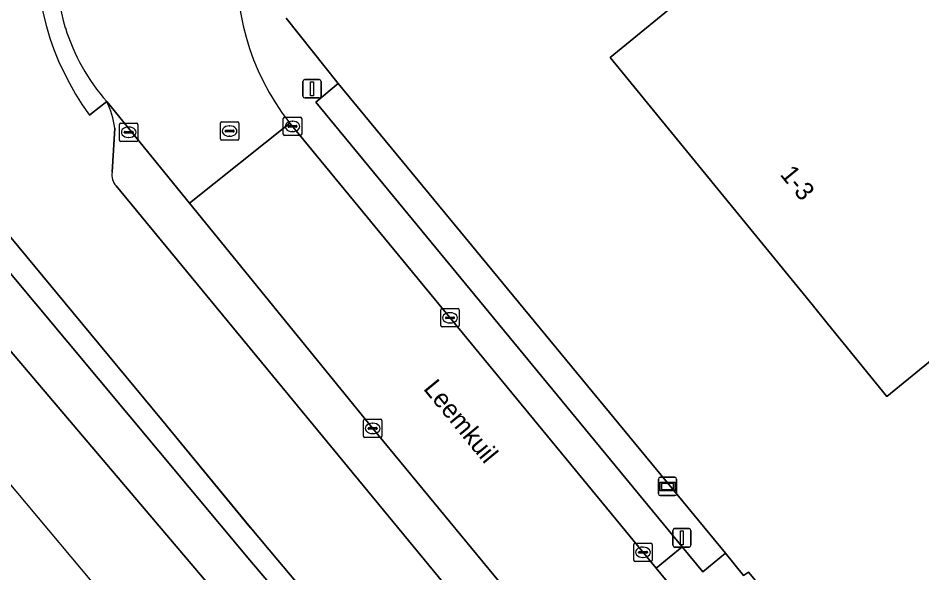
# Model space of a CAD drawing. Extents: x 156702 to 158052, y 387630 to 388992.
# Drawn here: x 156930.1 to 156979.28, y 388126.02 to 388156.23 of the extents above; entities that cross this region are included whole.
import ezdxf

# ---------------------------------------------------------------- set-up
doc = ezdxf.new("R2010")
doc.units = 0
for name, color, linetype in [('IMGEO_Berm_groen', 7, 'Continuous'), ('IMGEO_Erf', 7, 'Continuous'), ('IMGEO_Grasland_overig', 7, 'Continuous'), ('IMGEO_Groenvoorziening', 7, 'Continuous'), ('IMGEO_Hek', 7, 'Continuous'), ('IMGEO_Kolk', 7, 'Continuous'), ('IMGEO_Lichtmast', 7, 'Continuous'), ('IMGEO_Muur', 7, 'Continuous'), ('IMGEO_Openbare_ruimte_label', 7, 'Continuous'), ('IMGEO_Pand', 7, 'Continuous'), ('IMGEO_Pand_nummerreeks', 7, 'Continuous'), ('IMGEO_Parkeervlak_open', 7, 'Continuous'), ('IMGEO_Rijbaan_lokaal_gesloten', 7, 'Continuous'), ('IMGEO_Rioolput', 7, 'Continuous'), ('IMGEO_Spoor', 7, 'Continuous'), ('IMGEO_Spoorbaan_halfverhard', 7, 'Continuous'), ('IMGEO_Verkeerseiland_open', 7, 'Continuous'), ('IMGEO_Verklikker', 7, 'Continuous'), ('IMGEO_Voetpad_open', 7, 'Continuous')]:
    doc.layers.add(name, color=color, linetype=linetype)

msp = doc.modelspace()

# ---------------------------------------------------------------- linework, layer by layer
at = {"layer": 'IMGEO_Berm_groen'}
for points in [[(156896.099, 388207.526), (156898, 388209.126), (156929.184, 388170.168), (156924.251, 388165.972), (156893.783, 388204.247), (156893.53, 388204.428), (156892.646, 388205.059), (156888.807, 388202.728), (156887.763, 388201.954), (156884.553, 388200.49), (156886.404, 388196.476), (156888.178, 388194.608), (156891.399, 388190.784), (156894.533, 388186.892), (156900.926, 388179.065), (156905.729, 388173.299), (156910.538, 388167.48), (156920.203, 388155.732), (156923.432, 388151.842), (156933.092, 388140.181), (156937.906, 388134.372), (156942.722, 388128.504), (156944.225, 388126.72), (156950.711, 388119.018)], [(156934.916, 388151.692), (156934.087, 388151.032), (156933.977, 388150.944)], [(156935.21, 388147.831), (156935.356, 388150.243)], [(157082.395, 387968.454), (157010.543, 388055.913), (156935.425, 388147.089)]]:
    msp.add_lwpolyline(points, dxfattribs=at)
for centre, radius, start, end in [((156946.293, 388159.895), 15.225, 136.0002, 216.0083), ((156931.068, 388149.732), 4.318, 6.792, 26.9906), ((156936.179, 388147.71), 0.977, 172.8704, 219.4483)]:
    msp.add_arc(centre, radius, start, end, dxfattribs=at)
at = {"layer": 'IMGEO_Erf'}
for points in [[(156982.599, 388139.887), (156977.372, 388135.617), (156974.12, 388139.625), (156973.299, 388140.637), (156962.306, 388154.079), (156967.472, 388158.304), (156963.056, 388163.663), (156979.678, 388177.353)], [(156944.674, 388156.23), (156947.515, 388152.662), (156968.59, 388127.099), (156969.571, 388125.885), (156969.838, 388126.064), (156973.576, 388121.584)]]:
    msp.add_lwpolyline(points, dxfattribs=at)
at = {"layer": 'IMGEO_Grasland_overig'}
for points in [[(156950.711, 388119.018), (156944.225, 388126.72), (156942.722, 388128.504), (156937.906, 388134.372), (156933.092, 388140.181), (156923.432, 388151.842), (156920.203, 388155.732), (156910.538, 388167.48), (156905.729, 388173.299), (156900.926, 388179.065), (156894.533, 388186.892), (156891.399, 388190.784), (156888.178, 388194.608), (156886.404, 388196.476), (156884.553, 388200.49), (156883.204, 388198.755), (156897.934, 388180.367), (156942.697, 388126.718), (156967.711, 388097.26)], [(156967.711, 388097.26), (156942.697, 388126.718), (156897.934, 388180.367), (156883.204, 388198.755), (156881.34, 388197.231), (156885.921, 388191.403), (156911.81, 388159.683), (156929.103, 388138.77), (156962.414, 388099.504)]]:
    msp.add_lwpolyline(points, dxfattribs=at)
at = {"layer": 'IMGEO_Groenvoorziening'}
msp.add_lwpolyline([(156968.59, 388127.099), (156947.515, 388152.662), (156946.293, 388151.648), (156966.232, 388127.436), (156967.347, 388126.077)], close=True, dxfattribs=at)
at = {"layer": 'IMGEO_Hek'}
msp.add_lwpolyline([(156881.352, 388206.869), (156882.652, 388204.634), (156884.272, 388200.902), (156886.31, 388196.524), (156888.129, 388194.659), (156896.125, 388184.896), (156905.748, 388173.218), (156912.203, 388165.408), (156918.6, 388157.648), (156928.233, 388146.023), (156937.874, 388134.379), (156942.73, 388128.478)], dxfattribs=at)
at = {"layer": 'IMGEO_Kolk'}
for p, q in [((156944.601, 388150.832), (156945.453, 388150.832)), ((156935.614, 388149.587), (156935.614, 388150.439)), ((156935.689, 388150.513), (156936.541, 388150.513)), ((156936.615, 388150.439), (156936.615, 388149.587)), ((156944.526, 388149.906), (156944.526, 388150.758)), ((156944.785, 388150.326), (156944.785, 388150.338)), ((156944.828, 388150.375), (156945.226, 388150.375)), ((156945.014, 388150.612), (156945.039, 388150.612)), ((156945.269, 388150.338), (156945.269, 388150.326)), ((156945.527, 388150.758), (156945.527, 388149.906)), ((156935.873, 388150.007), (156935.873, 388150.019)), ((156936.311, 388149.97), (156935.913, 388149.97)), ((156935.916, 388150.056), (156936.314, 388150.056)), ((156936.102, 388150.293), (156936.127, 388150.293)), ((156936.357, 388150.019), (156936.357, 388150.007)), ((156945.453, 388149.832), (156944.601, 388149.832)), ((156945.223, 388150.289), (156944.825, 388150.289)), ((156945.037, 388150.052), (156945.012, 388150.052)), ((156936.541, 388149.513), (156935.689, 388149.513)), ((156936.125, 388149.733), (156936.1, 388149.733)), ((156953.096, 388139.484), (156953.096, 388140.336)), ((156953.171, 388140.41), (156954.023, 388140.41)), ((156953.584, 388140.19), (156953.609, 388140.19)), ((156954.097, 388140.336), (156954.097, 388139.484)), ((156953.355, 388139.904), (156953.355, 388139.916)), ((156953.793, 388139.867), (156953.395, 388139.867)), ((156953.398, 388139.953), (156953.796, 388139.953)), ((156953.607, 388139.63), (156953.582, 388139.63)), ((156953.839, 388139.916), (156953.839, 388139.904)), ((156954.023, 388139.41), (156953.171, 388139.41)), ((156948.889, 388133.462), (156948.889, 388134.314)), ((156948.964, 388134.388), (156949.816, 388134.388)), ((156949.377, 388134.168), (156949.402, 388134.168)), ((156949.89, 388134.314), (156949.89, 388133.462)), ((156949.148, 388133.882), (156949.148, 388133.894)), ((156949.586, 388133.845), (156949.188, 388133.845)), ((156949.191, 388133.931), (156949.589, 388133.931)), ((156949.4, 388133.608), (156949.375, 388133.608)), ((156949.632, 388133.894), (156949.632, 388133.882)), ((156949.816, 388133.388), (156948.964, 388133.388)), ((156963.599, 388126.717), (156963.599, 388127.569)), ((156963.674, 388127.643), (156964.526, 388127.643)), ((156963.901, 388127.186), (156964.299, 388127.186)), ((156964.087, 388127.423), (156964.112, 388127.423)), ((156964.6, 388127.569), (156964.6, 388126.717)), ((156963.858, 388127.137), (156963.858, 388127.149)), ((156964.296, 388127.1), (156963.898, 388127.1)), ((156964.11, 388126.863), (156964.085, 388126.863)), ((156964.342, 388127.149), (156964.342, 388127.137)), ((156964.526, 388126.643), (156963.674, 388126.643))]:
    msp.add_line(p, q, dxfattribs=at)
for points in [[(156944.601, 388150.832), (156945.453, 388150.832)], [(156935.614, 388149.587), (156935.614, 388150.439)], [(156935.689, 388150.513), (156936.541, 388150.513)], [(156936.615, 388150.439), (156936.615, 388149.587)], [(156944.526, 388149.906), (156944.526, 388150.758)], [(156945.527, 388150.758), (156945.527, 388149.906)], [(156945.453, 388149.832), (156944.601, 388149.832)], [(156936.541, 388149.513), (156935.689, 388149.513)], [(156953.096, 388139.484), (156953.096, 388140.336)], [(156953.171, 388140.41), (156954.023, 388140.41)], [(156954.097, 388140.336), (156954.097, 388139.484)], [(156954.023, 388139.41), (156953.171, 388139.41)], [(156948.889, 388133.462), (156948.889, 388134.314)], [(156948.964, 388134.388), (156949.816, 388134.388)], [(156949.89, 388134.314), (156949.89, 388133.462)], [(156949.816, 388133.388), (156948.964, 388133.388)], [(156963.599, 388126.717), (156963.599, 388127.569)], [(156963.674, 388127.643), (156964.526, 388127.643)], [(156964.6, 388127.569), (156964.6, 388126.717)], [(156964.526, 388126.643), (156963.674, 388126.643)]]:
    msp.add_lwpolyline(points, dxfattribs=at)
for centre, radius, start, end in [((156944.603, 388150.756), 0.0765, 91.552, 178.448), ((156944.603, 388150.756), 0.0765, 91.552, 178.448), ((156945.451, 388150.756), 0.0765, 1.552, 88.448), ((156945.451, 388150.756), 0.0765, 1.552, 88.448), ((156935.691, 388150.437), 0.0765, 91.552, 178.448), ((156935.691, 388150.437), 0.0765, 91.552, 178.448), ((156936.539, 388150.437), 0.0765, 1.552, 88.448), ((156936.539, 388150.437), 0.0765, 1.552, 88.448), ((156944.825, 388150.335), 0.0403, 85.8775, 175.7526), ((156944.822, 388150.325), 0.0366, 178.938, 274.7102), ((156945.226, 388150.332), 0.043, 264.8664, 352.4533), ((156945.23, 388150.337), 0.0386, 1.7309, 96.639), ((156935.913, 388150.016), 0.0403, 85.8775, 175.7526), ((156935.91, 388150.006), 0.0366, 178.938, 274.7102), ((156936.314, 388150.013), 0.043, 264.8664, 352.4533), ((156936.318, 388150.018), 0.0386, 1.7309, 96.639), ((156944.603, 388149.908), 0.0765, 181.552, 268.448), ((156944.603, 388149.908), 0.0765, 181.552, 268.448), ((156945.451, 388149.908), 0.0765, 271.552, 358.448), ((156945.451, 388149.908), 0.0765, 271.552, 358.448), ((156935.691, 388149.589), 0.0765, 181.552, 268.448), ((156935.691, 388149.589), 0.0765, 181.552, 268.448), ((156936.539, 388149.589), 0.0765, 271.552, 358.448), ((156936.539, 388149.589), 0.0765, 271.552, 358.448), ((156953.173, 388140.334), 0.0765, 91.552, 178.448), ((156953.173, 388140.334), 0.0765, 91.552, 178.448), ((156954.021, 388140.334), 0.0765, 1.552, 88.448), ((156954.021, 388140.334), 0.0765, 1.552, 88.448), ((156953.173, 388139.486), 0.0765, 181.552, 268.448), ((156953.173, 388139.486), 0.0765, 181.552, 268.448), ((156953.395, 388139.913), 0.0403, 85.8775, 175.7526), ((156953.392, 388139.903), 0.0366, 178.938, 274.7102), ((156953.796, 388139.91), 0.043, 264.8664, 352.4533), ((156953.8, 388139.915), 0.0386, 1.7309, 96.639), ((156954.021, 388139.486), 0.0765, 271.552, 358.448), ((156954.021, 388139.486), 0.0765, 271.552, 358.448), ((156948.966, 388134.312), 0.0765, 91.552, 178.448), ((156948.966, 388134.312), 0.0765, 91.552, 178.448), ((156949.814, 388134.312), 0.0765, 1.552, 88.448), ((156949.814, 388134.312), 0.0765, 1.552, 88.448), ((156949.188, 388133.891), 0.0403, 85.8775, 175.7526), ((156949.185, 388133.881), 0.0366, 178.938, 274.7102), ((156949.589, 388133.888), 0.043, 264.8664, 352.4533), ((156949.593, 388133.893), 0.0386, 1.7309, 96.639), ((156948.966, 388133.464), 0.0765, 181.552, 268.448), ((156948.966, 388133.464), 0.0765, 181.552, 268.448), ((156949.814, 388133.464), 0.0765, 271.552, 358.448), ((156949.814, 388133.464), 0.0765, 271.552, 358.448), ((156963.676, 388127.567), 0.0765, 91.552, 178.448), ((156963.676, 388127.567), 0.0765, 91.552, 178.448), ((156963.898, 388127.146), 0.0403, 85.8775, 175.7526), ((156964.303, 388127.148), 0.0386, 1.7309, 96.639), ((156964.524, 388127.567), 0.0765, 1.552, 88.448), ((156964.524, 388127.567), 0.0765, 1.552, 88.448), ((156963.676, 388126.719), 0.0765, 181.552, 268.448), ((156963.676, 388126.719), 0.0765, 181.552, 268.448), ((156963.895, 388127.136), 0.0366, 178.938, 274.7102), ((156964.299, 388127.143), 0.043, 264.8664, 352.4533), ((156964.524, 388126.719), 0.0765, 271.552, 358.448), ((156964.524, 388126.719), 0.0765, 271.552, 358.448)]:
    msp.add_arc(centre, radius, start, end, dxfattribs=at)
for centre, major_axis, ratio, start_param, end_param in [((156936.101, 388150.013), (-0.387, 0.002), 0.722429, 4.712389, 7.853982), ((156945.013, 388150.332), (-0.387, 0.002), 0.722429, 4.712389, 7.853982), ((156945.038, 388150.332), (-0.39, 0.002), 0.717154, 1.570796, 4.712389), ((156936.126, 388150.013), (-0.39, 0.002), 0.717154, 1.570796, 4.712389), ((156953.583, 388139.91), (-0.387, 0.002), 0.722429, 4.712389, 7.853982), ((156953.608, 388139.91), (-0.39, 0.002), 0.717154, 1.570796, 4.712389), ((156949.376, 388133.888), (-0.387, 0.002), 0.722429, 4.712389, 7.853982), ((156949.401, 388133.888), (-0.39, 0.002), 0.717154, 1.570796, 4.712389), ((156964.086, 388127.143), (-0.387, 0.002), 0.722429, 4.712389, 7.853982), ((156964.111, 388127.143), (-0.39, 0.002), 0.717154, 1.570796, 4.712389)]:
    msp.add_ellipse(centre, major_axis=major_axis, ratio=ratio, start_param=start_param, end_param=end_param, dxfattribs=at)
at = {"layer": 'IMGEO_Lichtmast'}
for p, q in [((156945.594, 388151.978), (156945.594, 388152.778)), ((156945.594, 388152.778), (156945.594, 388151.978)), ((156945.694, 388152.878), (156946.484, 388152.878)), ((156946.484, 388152.878), (156945.694, 388152.878)), ((156946.584, 388152.778), (156946.584, 388151.978)), ((156946.584, 388151.978), (156946.584, 388152.778)), ((156946.484, 388151.878), (156945.694, 388151.878)), ((156945.694, 388151.878), (156946.484, 388151.878)), ((156965.721, 388127.53), (156965.721, 388128.33)), ((156965.721, 388128.33), (156965.721, 388127.53)), ((156965.821, 388128.43), (156966.611, 388128.43)), ((156966.611, 388128.43), (156965.821, 388128.43)), ((156966.711, 388128.33), (156966.711, 388127.53)), ((156966.711, 388127.53), (156966.711, 388128.33)), ((156966.611, 388127.43), (156965.821, 388127.43)), ((156965.821, 388127.43), (156966.611, 388127.43))]:
    msp.add_line(p, q, dxfattribs=at)
for points in [[(156946.014, 388152.753), (156946.164, 388152.753), (156946.164, 388152.003), (156946.014, 388152.003), (156946.014, 388152.753)], [(156966.141, 388128.305), (156966.291, 388128.305), (156966.291, 388127.555), (156966.141, 388127.555), (156966.141, 388128.305)]]:
    msp.add_lwpolyline(points, dxfattribs=at)
for centre, start, end in [((156945.694, 388152.778), 90, 180), ((156945.694, 388152.778), 90, 180), ((156946.484, 388152.778), 0, 90), ((156946.484, 388152.778), 360, 90), ((156945.694, 388151.978), 180, 270), ((156945.694, 388151.978), 180, 270), ((156946.484, 388151.978), 270, 0), ((156946.484, 388151.978), 270, 0), ((156965.821, 388128.33), 90, 180), ((156965.821, 388128.33), 90, 180), ((156966.611, 388128.33), 0, 90), ((156966.611, 388128.33), 360, 90), ((156965.821, 388127.53), 180, 270), ((156965.821, 388127.53), 180, 270), ((156966.611, 388127.53), 270, 0), ((156966.611, 388127.53), 270, 0)]:
    msp.add_arc(centre, 0.1, start, end, dxfattribs=at)
at = {"layer": 'IMGEO_Muur'}
msp.add_lwpolyline([(156884.553, 388200.49), (156886.404, 388196.476), (156888.178, 388194.608), (156891.399, 388190.784), (156894.533, 388186.892), (156900.926, 388179.065), (156905.729, 388173.299), (156910.538, 388167.48), (156920.203, 388155.732), (156923.432, 388151.842), (156933.092, 388140.181), (156937.906, 388134.372), (156942.722, 388128.504), (156944.225, 388126.72), (156950.711, 388119.018)], dxfattribs=at)
at = {"layer": 'IMGEO_Pand'}
msp.add_lwpolyline([(156979.678, 388177.353), (156963.056, 388163.663), (156967.472, 388158.304), (156962.306, 388154.079), (156973.299, 388140.637), (156974.12, 388139.625), (156977.372, 388135.617), (156982.599, 388139.887), (156986.971, 388134.536), (157000, 388145.263), (157003.589, 388148.218), (157000, 388152.592)], close=True, dxfattribs=at)
at = {"layer": 'IMGEO_Parkeervlak_open'}
for points in [[(156975.736, 388101.937), (156949.39, 388133.888), (156939.424, 388146.146), (156934.916, 388151.692)], [(156935.356, 388150.243), (156935.21, 388147.831)], [(156935.425, 388147.089), (157010.543, 388055.913), (157082.395, 387968.454)]]:
    msp.add_lwpolyline(points, dxfattribs=at)
for centre, radius, start, end in [((156931.068, 388149.732), 4.318, 6.792, 26.9906), ((156936.179, 388147.71), 0.977, 172.8704, 219.4483)]:
    msp.add_arc(centre, radius, start, end, dxfattribs=at)
at = {"layer": 'IMGEO_Rijbaan_lokaal_gesloten'}
for points in [[(156934.916, 388151.692), (156939.424, 388146.146), (156944.879, 388150.503)], [(156973.268, 388116.017), (156964.812, 388126.277), (156944.879, 388150.503), (156939.424, 388146.146), (156949.39, 388133.888), (156975.736, 388101.937)]]:
    msp.add_lwpolyline(points, dxfattribs=at)
for centre, radius, start, end in [((156955.642, 388158.903), 13.653, 130.6832, 217.97), ((156944.671, 388159.255), 12.52, 166.7289, 196.4964), ((156943.228, 388158.991), 11.062, 197.3081, 221.2879)]:
    msp.add_arc(centre, radius, start, end, dxfattribs=at)
at = {"layer": 'IMGEO_Rioolput'}
for p, q in [((156941.102, 388149.651), (156941.102, 388150.503)), ((156941.177, 388150.577), (156942.029, 388150.577)), ((156941.59, 388150.357), (156941.615, 388150.357)), ((156942.103, 388150.503), (156942.103, 388149.651)), ((156941.361, 388150.071), (156941.361, 388150.083)), ((156941.799, 388150.034), (156941.401, 388150.034)), ((156941.404, 388150.12), (156941.802, 388150.12)), ((156941.845, 388150.083), (156941.845, 388150.071)), ((156942.029, 388149.577), (156941.177, 388149.577)), ((156941.613, 388149.797), (156941.588, 388149.797))]:
    msp.add_line(p, q, dxfattribs=at)
for points in [[(156941.102, 388149.651), (156941.102, 388150.503)], [(156941.177, 388150.577), (156942.029, 388150.577)], [(156942.103, 388150.503), (156942.103, 388149.651)], [(156942.029, 388149.577), (156941.177, 388149.577)]]:
    msp.add_lwpolyline(points, dxfattribs=at)
for centre, radius, start, end in [((156941.179, 388150.501), 0.0765, 91.552, 178.448), ((156941.179, 388150.501), 0.0765, 91.552, 178.448), ((156942.027, 388150.501), 0.0765, 1.552, 88.448), ((156942.027, 388150.501), 0.0765, 1.552, 88.448), ((156941.401, 388150.08), 0.0403, 85.8775, 175.7526), ((156941.398, 388150.07), 0.0366, 178.938, 274.7102), ((156941.802, 388150.077), 0.043, 264.8664, 352.4533), ((156941.806, 388150.082), 0.0386, 1.7309, 96.639), ((156941.179, 388149.653), 0.0765, 181.552, 268.448), ((156941.179, 388149.653), 0.0765, 181.552, 268.448), ((156942.027, 388149.653), 0.0765, 271.552, 358.448), ((156942.027, 388149.653), 0.0765, 271.552, 358.448)]:
    msp.add_arc(centre, radius, start, end, dxfattribs=at)
for centre, major_axis, ratio, start_param, end_param in [((156941.589, 388150.077), (-0.387, 0.002), 0.722429, 4.712389, 7.853982), ((156941.614, 388150.077), (-0.39, 0.002), 0.717154, 1.570796, 4.712389)]:
    msp.add_ellipse(centre, major_axis=major_axis, ratio=ratio, start_param=start_param, end_param=end_param, dxfattribs=at)
at = {"layer": 'IMGEO_Spoor'}
msp.add_lwpolyline([(156872.422, 388201.343), (156882.919, 388187.987), (156900.381, 388166.18), (156921.457, 388140.635), (156943.252, 388114.607), (156960.211, 388094.663), (156986.26, 388064.316), (157082.584, 387953.12), (157127.585, 387900.649), (157147.691, 387876.906), (157152.061, 387871.615)], dxfattribs=at)
at = {"layer": 'IMGEO_Spoorbaan_halfverhard'}
msp.add_lwpolyline([(156962.414, 388099.504), (156929.103, 388138.77)], dxfattribs=at)
at = {"layer": 'IMGEO_Verkeerseiland_open'}
msp.add_lwpolyline([(156933.977, 388150.944), (156934.087, 388151.032), (156934.916, 388151.692)], dxfattribs=at)
for centre, radius, start, end in [((156946.293, 388159.895), 15.225, 136.0002, 216.0083), ((156944.671, 388159.255), 12.52, 166.7289, 196.4964), ((156943.228, 388158.991), 11.062, 197.3081, 221.2879)]:
    msp.add_arc(centre, radius, start, end, dxfattribs=at)
at = {"layer": 'IMGEO_Verklikker'}
for p, q in [((156964.937, 388130.329), (156964.937, 388131.129)), ((156964.937, 388131.129), (156964.937, 388130.329)), ((156965.037, 388131.229), (156965.827, 388131.229)), ((156965.827, 388131.229), (156965.037, 388131.229)), ((156965.927, 388131.129), (156965.927, 388130.329)), ((156965.927, 388130.329), (156965.927, 388131.129)), ((156965.827, 388130.229), (156965.037, 388130.229)), ((156965.037, 388130.229), (156965.827, 388130.229))]:
    msp.add_line(p, q, dxfattribs=at)
for points in [[(156965.038, 388130.961), (156965.826, 388130.961), (156965.826, 388130.497), (156965.038, 388130.497), (156965.038, 388130.961)], [(156965.103, 388130.896), (156965.103, 388130.562), (156965.761, 388130.562), (156965.761, 388130.896), (156965.103, 388130.896)]]:
    msp.add_lwpolyline(points, dxfattribs=at)
for centre, start, end in [((156965.037, 388131.129), 90, 180), ((156965.037, 388131.129), 90, 180), ((156965.827, 388131.129), 0, 90), ((156965.827, 388131.129), 360, 90), ((156965.037, 388130.329), 180, 270), ((156965.037, 388130.329), 180, 270), ((156965.827, 388130.329), 270, 0), ((156965.827, 388130.329), 270, 0)]:
    msp.add_arc(centre, 0.1, start, end, dxfattribs=at)
at = {"layer": 'IMGEO_Voetpad_open'}
msp.add_lwpolyline([(156944.879, 388150.503), (156964.812, 388126.277), (156966.232, 388127.436), (156946.293, 388151.648), (156947.515, 388152.662), (156944.674, 388156.23)], dxfattribs=at)
msp.add_lwpolyline([(156973.268, 388116.017), (156974.681, 388117.172), (156973.01, 388119.173), (156974.286, 388120.211), (156973.316, 388121.36), (156973.576, 388121.584), (156969.838, 388126.064), (156969.571, 388125.885), (156968.59, 388127.099), (156967.347, 388126.077), (156966.232, 388127.436), (156964.812, 388126.277)], close=True, dxfattribs=at)
msp.add_arc((156955.642, 388158.903), 13.653, 130.6832, 217.97, dxfattribs=at)

# ---------------------------------------------------------------- texts
at = {"layer": 'IMGEO_Openbare_ruimte_label'}
msp.add_text('Leemkuil', height=1, rotation=309.4386, dxfattribs=at).set_placement((156952.11, 388136.036))
at = {"layer": 'IMGEO_Pand_nummerreeks'}
msp.add_text('1-3', height=1, rotation=309.3162, dxfattribs=at).set_placement((156971.515, 388147.703))

doc.saveas('drawing.dxf')
